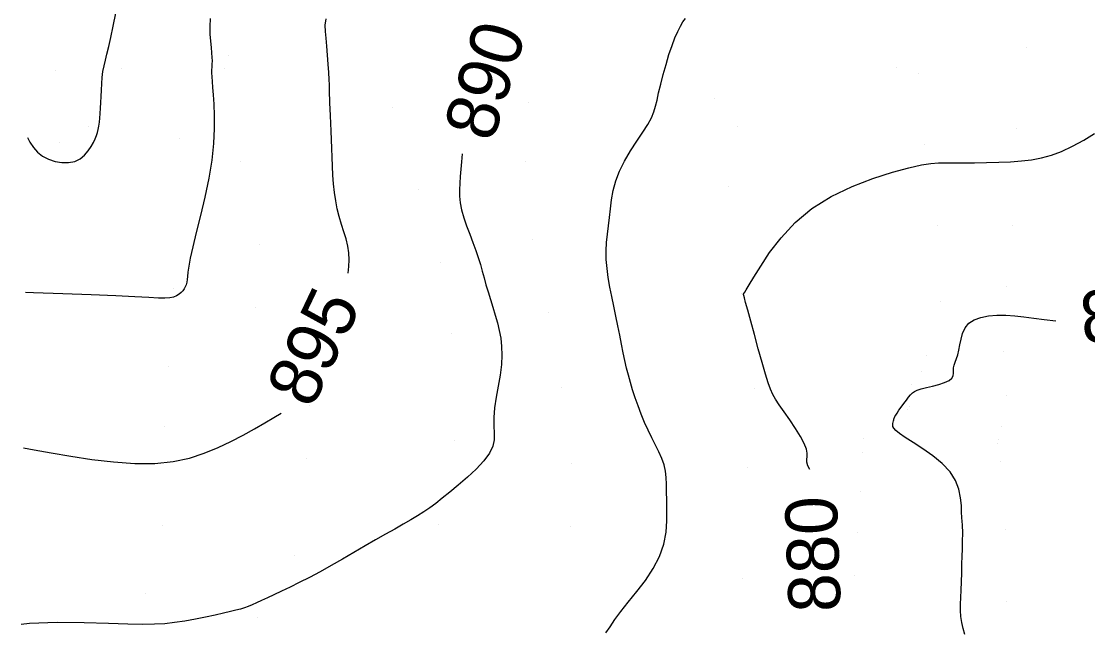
# Model space of a CAD drawing. Extents: x 400243 to 403697, y 4403637 to 4408083.
# Drawn here: x 402558.6 to 402712.4, y 4406214.4 to 4406302.1 of the extents above; entities that cross this region are included whole.
import ezdxf

# ---------------------------------------------------------------- set-up
doc = ezdxf.new("R2010")
doc.units = 0
doc.layers.add('HH_IC', color=7, linetype='Continuous')

msp = doc.modelspace()

# ---------------------------------------------------------------- linework, layer by layer
at = {"layer": 'HH_IC'}
for p, q in [((402703.55, 4406298.33), (402703.55, 4406298.33)), ((402588.44, 4406297.17), (402588.44, 4406297.17)), ((402563.57, 4406295.06), (402563.57, 4406295.06)), ((402573.01, 4406295.28), (402573.01, 4406295.28)), ((402587.83, 4406295.27), (402587.83, 4406295.27)), ((402684.73, 4406295.51), (402684.73, 4406295.51)), ((402688.03, 4406294.59), (402688.03, 4406294.59)), ((402631.78, 4406290.37), (402631.78, 4406290.37)), ((402658.55, 4406290.96), (402658.55, 4406290.96)), ((402612.08, 4406289.61), (402612.08, 4406289.61)), ((402568.3, 4406286.91), (402568.3, 4406286.91)), ((402661.93, 4406286.91), (402661.93, 4406286.91)), ((402702.03, 4406286.58), (402702.03, 4406286.58)), ((402564.02, 4406284.67), (402564.02, 4406284.67)), ((402581.37, 4406285.2), (402581.37, 4406285.2)), ((402688.83, 4406284.28), (402688.83, 4406284.28)), ((402590.22, 4406281.87), (402590.22, 4406281.87)), ((402631.24, 4406281.84), (402631.24, 4406281.84)), ((402615.87, 4406277.84), (402615.87, 4406277.84)), ((402660.61, 4406278.32), (402660.61, 4406278.32)), ((402690.63, 4406272.72), (402690.63, 4406272.72)), ((402701.55, 4406272.67), (402701.55, 4406272.67)), ((402632.26, 4406270.61), (402632.26, 4406270.61)), ((402592.99, 4406269.96), (402592.99, 4406269.96)), ((402619.03, 4406267.35), (402619.03, 4406267.35)), ((402580.56, 4406263.59), (402580.56, 4406263.59)), ((402662.47, 4406262.83), (402662.47, 4406262.83)), ((402700.62, 4406263.86), (402700.62, 4406263.86)), ((402691.14, 4406261.69), (402691.14, 4406261.69)), ((402592.37, 4406260.83), (402592.37, 4406260.83)), ((402634.66, 4406260.12), (402634.66, 4406260.12)), ((402620.68, 4406257.05), (402620.68, 4406257.05)), ((402689.13, 4406253.9), (402689.13, 4406253.9)), ((402700.28, 4406254.52), (402700.28, 4406254.52)), ((402579.76, 4406252.34), (402579.76, 4406252.34)), ((402688.37, 4406251.65), (402688.37, 4406251.65)), ((402636.5, 4406249.27), (402636.5, 4406249.27)), ((402664.31, 4406249.15), (402664.31, 4406249.15)), ((402687.02, 4406249.71), (402687.02, 4406249.71)), ((402700.64, 4406248.13), (402700.64, 4406248.13)), ((402600.2, 4406246.73), (402600.2, 4406246.73)), ((402686.42, 4406246.11), (402686.42, 4406246.11)), ((402686.6, 4406246.64), (402686.6, 4406246.64)), ((402579.21, 4406243.65), (402579.21, 4406243.65)), ((402699.93, 4406243.67), (402699.93, 4406243.67)), ((402621.1, 4406241.62), (402621.1, 4406241.62)), ((402680.03, 4406242.01), (402680.03, 4406242.01)), ((402699.38, 4406241.27), (402699.38, 4406241.27)), ((402699.56, 4406241.87), (402699.56, 4406241.87)), ((402679.84, 4406239.98), (402679.84, 4406239.98)), ((402599.76, 4406239.11), (402599.76, 4406239.11)), ((402637.87, 4406238.41), (402637.87, 4406238.41)), ((402663.34, 4406237.8), (402663.34, 4406237.8)), ((402699.78, 4406238.59), (402699.78, 4406238.59)), ((402679.59, 4406234.29), (402679.59, 4406234.29)), ((402579.01, 4406229.46), (402579.01, 4406229.46)), ((402618.81, 4406229.59), (402618.81, 4406229.59)), ((402637.8, 4406229.23), (402637.8, 4406229.23)), ((402700.48, 4406228.85), (402700.48, 4406228.85)), ((402679.21, 4406228.42), (402679.21, 4406228.42)), ((402597.93, 4406225.07), (402597.93, 4406225.07)), ((402662.62, 4406221.74), (402662.62, 4406221.74)), ((402678.69, 4406222.25), (402678.69, 4406222.25)), ((402576.51, 4406219.55), (402576.51, 4406219.55)), ((402700.59, 4406218.4), (402700.59, 4406218.4)), ((402592.6, 4406216.19), (402592.6, 4406216.19))]:
    msp.add_line(p, q, dxfattribs=at)
for points in [[(402585.82, 4406302.49), (402585.75, 4406301.34), (402585.77, 4406300.25), (402585.85, 4406299.23), (402585.95, 4406298.32), (402586.03, 4406297.54), (402586.07, 4406296.9), (402586.08, 4406296.38), (402586.06, 4406295.93), (402586.04, 4406295.51), (402586.02, 4406295.1), (402586.02, 4406294.65), (402586.04, 4406294.1), (402586.08, 4406293.43), (402586.14, 4406292.57), (402586.23, 4406291.48), (402586.33, 4406290.13), (402586.4, 4406288.51), (402586.41, 4406286.63), (402586.31, 4406284.49), (402586.05, 4406282.09), (402585.6, 4406279.47), (402585.03, 4406276.76), (402584.41, 4406274.1), (402583.81, 4406271.66), (402583.31, 4406269.58), (402582.95, 4406267.97), (402582.74, 4406266.79), (402582.61, 4406265.93), (402582.54, 4406265.32), (402582.49, 4406264.86), (402582.43, 4406264.47), (402582.34, 4406264.12), (402582.21, 4406263.81), (402582.06, 4406263.53), (402581.86, 4406263.25), (402581.63, 4406262.99), (402581.33, 4406262.74), (402580.97, 4406262.52), (402580.52, 4406262.35), (402579.98, 4406262.24), (402579.3, 4406262.19), (402578.35, 4406262.21), (402576.96, 4406262.28), (402574.97, 4406262.39), (402572.22, 4406262.52), (402568.65, 4406262.67), (402564.55, 4406262.82), (402560.34, 4406262.96), (402559.19, 4406262.99)], [(402559.48, 4406285.33), (402559.81, 4406284.67), (402560.32, 4406283.9), (402560.92, 4406283.23), (402561.65, 4406282.67), (402562.5, 4406282.22), (402563.45, 4406281.9), (402564.44, 4406281.73), (402565.4, 4406281.73), (402566.29, 4406281.91), (402567.05, 4406282.28), (402567.69, 4406282.8), (402568.22, 4406283.41), (402568.64, 4406284.04), (402568.98, 4406284.64), (402569.23, 4406285.16), (402569.43, 4406285.63), (402569.57, 4406286.07), (402569.68, 4406286.51), (402569.77, 4406287), (402569.85, 4406287.54), (402569.91, 4406288.15), (402569.97, 4406288.83), (402570.02, 4406289.58), (402570.06, 4406290.39), (402570.1, 4406291.27), (402570.14, 4406292.19), (402570.18, 4406293.12), (402570.26, 4406294.02), (402570.36, 4406294.88), (402570.51, 4406295.68), (402570.7, 4406296.49), (402570.93, 4406297.38), (402571.2, 4406298.45), (402571.51, 4406299.77), (402571.85, 4406301.4), (402572.22, 4406303.27)], [(402605.7, 4406265.8), (402605.8, 4406266.76), (402605.86, 4406267.72), (402605.83, 4406268.7), (402605.67, 4406269.69), (402605.41, 4406270.72), (402605.08, 4406271.76), (402604.73, 4406272.83), (402604.41, 4406273.94), (402604.13, 4406275.07), (402603.92, 4406276.24), (402603.75, 4406277.44), (402603.62, 4406278.66), (402603.52, 4406279.92), (402603.45, 4406281.2), (402603.39, 4406282.49), (402603.35, 4406283.78), (402603.32, 4406285.04), (402603.28, 4406286.26), (402603.23, 4406287.42), (402603.18, 4406288.49), (402603.13, 4406289.46), (402603.08, 4406290.3), (402603.05, 4406290.99), (402603.04, 4406291.51), (402603.03, 4406291.95), (402603.03, 4406292.4), (402603.01, 4406292.95), (402602.98, 4406293.7), (402602.92, 4406294.72), (402602.85, 4406295.92), (402602.75, 4406297.22), (402602.65, 4406298.5), (402602.54, 4406299.66), (402602.44, 4406300.65), (402602.41, 4406301.53), (402602.52, 4406302.44)], [(402642.87, 4406213.94), (402643.49, 4406214.83), (402644.18, 4406215.85), (402645.03, 4406217.02), (402646.11, 4406218.37), (402647.33, 4406219.88), (402648.57, 4406221.5), (402649.71, 4406223.21), (402650.62, 4406224.96), (402651.22, 4406226.72), (402651.55, 4406228.44), (402651.68, 4406230.1), (402651.69, 4406231.65), (402651.65, 4406233.06), (402651.64, 4406234.29), (402651.62, 4406235.37), (402651.57, 4406236.35), (402651.46, 4406237.27), (402651.26, 4406238.17), (402650.94, 4406239.09), (402650.52, 4406240.04), (402650.03, 4406241.02), (402649.5, 4406242.06), (402648.97, 4406243.14), (402648.45, 4406244.28), (402647.97, 4406245.46), (402647.51, 4406246.65), (402647.1, 4406247.82), (402646.73, 4406248.95), (402646.41, 4406250.03), (402646.12, 4406251.08), (402645.87, 4406252.12), (402645.63, 4406253.19), (402645.39, 4406254.33), (402645.14, 4406255.56), (402644.88, 4406256.86), (402644.61, 4406258.21), (402644.33, 4406259.61), (402644.04, 4406261.01), (402643.75, 4406262.41), (402643.47, 4406263.79), (402643.23, 4406265.15), (402643.05, 4406266.47), (402642.94, 4406267.76), (402642.93, 4406269), (402642.99, 4406270.21), (402643.1, 4406271.4), (402643.24, 4406272.6), (402643.39, 4406273.82), (402643.53, 4406275.07), (402643.69, 4406276.37), (402643.93, 4406277.7), (402644.3, 4406279.08), (402644.84, 4406280.5), (402645.58, 4406281.96), (402646.45, 4406283.41), (402647.36, 4406284.8), (402648.23, 4406286.1), (402648.95, 4406287.23), (402649.46, 4406288.19), (402649.81, 4406289.04), (402650.05, 4406289.86), (402650.25, 4406290.74), (402650.48, 4406291.77), (402650.78, 4406293.02), (402651.14, 4406294.41), (402651.55, 4406295.86), (402651.98, 4406297.29), (402652.42, 4406298.59), (402652.84, 4406299.71), (402653.23, 4406300.63), (402653.62, 4406301.4), (402653.99, 4406302.01), (402654.35, 4406302.51)], [(402672.27, 4406237.48), (402672.02, 4406238.04), (402671.88, 4406238.53), (402671.85, 4406238.95), (402671.89, 4406239.37), (402671.89, 4406239.84), (402671.79, 4406240.44), (402671.49, 4406241.23), (402670.95, 4406242.24), (402670.21, 4406243.42), (402669.4, 4406244.64), (402668.59, 4406245.81), (402667.88, 4406246.83), (402667.34, 4406247.63), (402666.94, 4406248.32), (402666.6, 4406249.05), (402666.28, 4406249.98), (402665.89, 4406251.24), (402665.41, 4406252.93), (402664.86, 4406254.9), (402664.29, 4406256.95), (402663.76, 4406258.87), (402663.33, 4406260.46), (402663.03, 4406261.56), (402662.85, 4406262.24), (402662.75, 4406262.59), (402662.72, 4406262.72), (402662.71, 4406262.75), (402662.71, 4406262.76), (402662.72, 4406262.78), (402662.72, 4406262.8), (402662.73, 4406262.81), (402662.75, 4406262.84), (402662.79, 4406262.88), (402662.9, 4406263.04), (402663.13, 4406263.41), (402663.56, 4406264.09), (402664.23, 4406265.2), (402665.2, 4406266.8), (402666.49, 4406268.76), (402668.14, 4406270.9), (402670.17, 4406273.08), (402672.58, 4406275.1), (402675.38, 4406276.85), (402678.39, 4406278.29), (402681.39, 4406279.45), (402684.19, 4406280.35), (402686.56, 4406280.99), (402688.37, 4406281.4), (402689.73, 4406281.62), (402690.83, 4406281.71), (402691.87, 4406281.72), (402693.01, 4406281.7), (402694.42, 4406281.69), (402696.03, 4406281.7), (402697.76, 4406281.73), (402699.53, 4406281.78), (402701.23, 4406281.86), (402702.8, 4406281.97), (402704.27, 4406282.13), (402705.69, 4406282.4), (402707.12, 4406282.79), (402708.6, 4406283.34), (402710.17, 4406284.09), (402711.78, 4406284.97), (402713.35, 4406285.94)], [(402622.16, 4406282.98), (402622.06, 4406281.86), (402621.97, 4406280.77), (402621.88, 4406279.72), (402621.8, 4406278.75), (402621.76, 4406277.81), (402621.78, 4406276.89), (402621.87, 4406275.93), (402622.07, 4406274.9), (402622.39, 4406273.79), (402622.8, 4406272.61), (402623.25, 4406271.4), (402623.71, 4406270.21), (402624.13, 4406269.08), (402624.48, 4406268.03), (402624.78, 4406267.04), (402625.05, 4406266.08), (402625.31, 4406265.12), (402625.59, 4406264.13), (402625.9, 4406263.09), (402626.23, 4406262), (402626.58, 4406260.88), (402626.92, 4406259.75), (402627.23, 4406258.63), (402627.5, 4406257.52), (402627.72, 4406256.4), (402627.85, 4406255.24), (402627.89, 4406253.98), (402627.82, 4406252.61), (402627.63, 4406251.1), (402627.36, 4406249.5), (402627.07, 4406247.9), (402626.84, 4406246.37), (402626.71, 4406244.98), (402626.71, 4406243.79), (402626.76, 4406242.74), (402626.76, 4406241.78), (402626.58, 4406240.83), (402626.11, 4406239.83), (402625.29, 4406238.72), (402624.18, 4406237.54), (402622.91, 4406236.36), (402621.6, 4406235.23), (402620.36, 4406234.21), (402619.29, 4406233.35), (402618.35, 4406232.61), (402617.48, 4406231.97), (402616.63, 4406231.38), (402615.73, 4406230.81), (402614.74, 4406230.21), (402613.64, 4406229.59), (402612.43, 4406228.91), (402611.11, 4406228.17), (402609.68, 4406227.36), (402608.15, 4406226.47), (402606.55, 4406225.53), (402604.91, 4406224.57), (402603.26, 4406223.63), (402601.66, 4406222.73), (402600.12, 4406221.92), (402598.67, 4406221.18), (402597.33, 4406220.53), (402596.1, 4406219.94), (402595.01, 4406219.43), (402594.06, 4406218.98), (402593.24, 4406218.6), (402592.52, 4406218.27), (402591.88, 4406217.99), (402591.3, 4406217.75), (402590.75, 4406217.55), (402590.17, 4406217.37), (402589.52, 4406217.19), (402588.73, 4406217), (402587.75, 4406216.77), (402586.54, 4406216.5), (402585.16, 4406216.2), (402583.68, 4406215.9), (402582.16, 4406215.63), (402580.69, 4406215.41), (402579.28, 4406215.26), (402577.81, 4406215.18), (402576.09, 4406215.16), (402573.93, 4406215.19), (402571.15, 4406215.27), (402567.66, 4406215.37), (402563.74, 4406215.41), (402559.74, 4406215.27), (402558.58, 4406215.14)], [(402694.65, 4406213.7), (402694.39, 4406214.58), (402694.19, 4406215.45), (402694.07, 4406216.3), (402694.02, 4406217.16), (402694.03, 4406218.06), (402694.08, 4406219.03), (402694.13, 4406220.11), (402694.17, 4406221.3), (402694.21, 4406222.57), (402694.23, 4406223.82), (402694.26, 4406225), (402694.28, 4406226.02), (402694.3, 4406226.84), (402694.32, 4406227.47), (402694.33, 4406227.96), (402694.34, 4406228.37), (402694.33, 4406228.73), (402694.31, 4406229.09), (402694.28, 4406229.49), (402694.25, 4406229.98), (402694.21, 4406230.58), (402694.18, 4406231.35), (402694.14, 4406232.31), (402694.03, 4406233.42), (402693.78, 4406234.63), (402693.3, 4406235.89), (402692.52, 4406237.14), (402691.39, 4406238.35), (402690.03, 4406239.47), (402688.59, 4406240.49), (402687.21, 4406241.38), (402686.06, 4406242.12), (402685.23, 4406242.7), (402684.7, 4406243.13), (402684.4, 4406243.46), (402684.27, 4406243.71), (402684.24, 4406243.93), (402684.25, 4406244.12), (402684.29, 4406244.31), (402684.33, 4406244.48), (402684.38, 4406244.63), (402684.42, 4406244.76), (402684.45, 4406244.87), (402684.49, 4406244.99), (402684.55, 4406245.13), (402684.67, 4406245.33), (402684.86, 4406245.62), (402685.14, 4406246.02), (402685.48, 4406246.49), (402685.85, 4406246.99), (402686.21, 4406247.48), (402686.54, 4406247.92), (402686.81, 4406248.26), (402687.08, 4406248.53), (402687.38, 4406248.75), (402687.79, 4406248.94), (402688.36, 4406249.12), (402689.12, 4406249.31), (402690, 4406249.52), (402690.9, 4406249.76), (402691.72, 4406250.02), (402692.36, 4406250.31), (402692.75, 4406250.64), (402692.94, 4406250.99), (402693, 4406251.36), (402693, 4406251.75), (402693.01, 4406252.15), (402693.1, 4406252.55), (402693.24, 4406252.98), (402693.42, 4406253.47), (402693.61, 4406254.03), (402693.78, 4406254.68), (402693.93, 4406255.45), (402694.09, 4406256.28), (402694.32, 4406257.11), (402694.68, 4406257.89), (402695.22, 4406258.56), (402695.98, 4406259.07), (402696.94, 4406259.42), (402698.05, 4406259.64), (402699.26, 4406259.73), (402700.53, 4406259.73), (402701.83, 4406259.64), (402703.17, 4406259.5), (402704.58, 4406259.31), (402706.09, 4406259.11), (402707.74, 4406258.91)], [(402558.91, 4406240.61), (402560.43, 4406240.33), (402562.91, 4406239.89), (402565.71, 4406239.41), (402568.74, 4406238.95), (402571.86, 4406238.57), (402574.94, 4406238.35), (402577.84, 4406238.35), (402580.46, 4406238.62), (402582.83, 4406239.13), (402584.97, 4406239.82), (402586.95, 4406240.64), (402588.8, 4406241.54), (402590.56, 4406242.46), (402592.2, 4406243.36), (402593.69, 4406244.21), (402594.99, 4406244.97), (402596.07, 4406245.62)]]:
    msp.add_lwpolyline(points, dxfattribs=at)

# ---------------------------------------------------------------- texts
for s, rotation, p in [('890', 73.0453, (402626.54, 4406284.5)), ('875', 6.0383, (402711.67, 4406255.56)), ('895', 64.4947, (402600.44, 4406246.05)), ('880', 92.0575, (402676.76, 4406217.04))]:
    msp.add_text(s, height=7.5, rotation=rotation, dxfattribs=at).set_placement(p)

doc.saveas('drawing.dxf')
